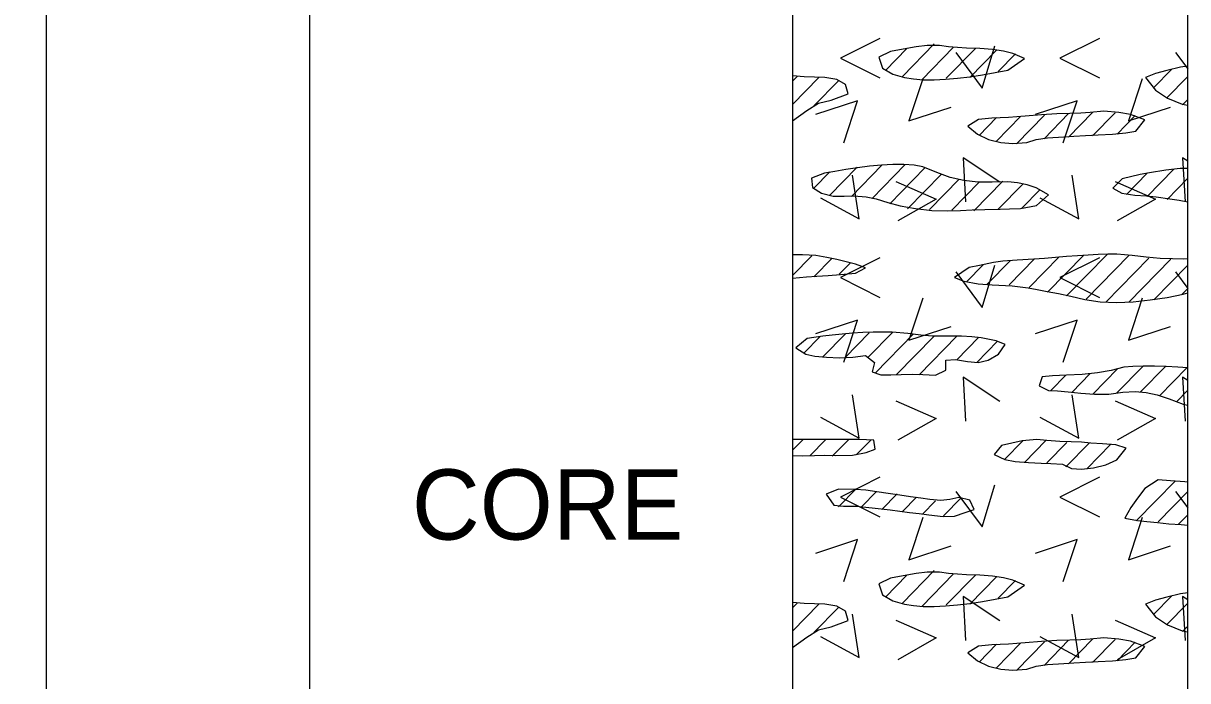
# Model space of a CAD drawing. Extents: x 0 to 0.833, y -0.32 to 0.608.
# Drawn here: x 0.7228 to 0.8333, y -0.0591 to 0.0033 of the extents above; entities that cross this region are included whole.
import ezdxf

# ---------------------------------------------------------------- set-up
doc = ezdxf.new("R2010")
doc.units = 0

msp = doc.modelspace()

# ---------------------------------------------------------------- linework, layer by layer
for points in [[(0, -0.32004), (0.83333, -0.32004), (0.83333, 0.60833), (0, 0.60833)], [(0.81233, 0.00099), (0.81063, 0.00111), (0.80977, 0.00124), (0.8086, 0.00125), (0.80755, 0.0011), (0.80632, 0.0009), (0.80513, 0.00066), (0.80403, 0.00014), (0.80436, -0.00092), (0.80536, -0.00149), (0.80647, -0.00179), (0.8073, -0.00194), (0.80824, -0.00201), (0.80926, -0.00202), (0.81035, -0.00197), (0.81149, -0.00187), (0.81267, -0.00172), (0.81386, -0.00154), (0.81506, -0.00132), (0.81625, -0.00109), (0.81783, -0.00001), (0.81673, 0.00049), (0.81585, 0.00069), (0.8148, 0.00085), (0.81361, 0.00095)], [(0.83265, -0.00082), (0.83136, -0.00113), (0.83028, -0.00141), (0.82934, -0.0018), (0.83026, -0.003), (0.83142, -0.00377), (0.83279, -0.00434), (0.83333, -0.00444), (0.83333, -0.00073)], [(0.79583, -0.00592), (0.79719, -0.00493), (0.79831, -0.00423), (0.79951, -0.00396), (0.80111, -0.00336), (0.80086, -0.00247), (0.80002, -0.002), (0.79889, -0.0018), (0.79791, -0.00177), (0.79694, -0.00172), (0.79583, -0.00163)], [(0.82537, -0.00498), (0.82408, -0.00513), (0.82319, -0.00518), (0.82214, -0.00521), (0.82091, -0.00525), (0.81947, -0.00534), (0.81792, -0.00546), (0.81632, -0.00558), (0.81475, -0.00567), (0.81348, -0.00577), (0.81247, -0.00641), (0.81337, -0.00717), (0.81444, -0.00768), (0.81561, -0.00796), (0.81675, -0.00807), (0.81807, -0.00796), (0.81896, -0.00768), (0.82003, -0.00754), (0.82157, -0.00742), (0.82253, -0.00736), (0.82362, -0.0073), (0.82483, -0.00724), (0.82618, -0.00717), (0.82745, -0.00706), (0.82842, -0.00689), (0.82927, -0.00583), (0.82791, -0.00532), (0.82679, -0.00512)], [(0.79885, -0.01089), (0.79763, -0.01135), (0.79773, -0.01224), (0.79859, -0.01277), (0.7997, -0.01306), (0.80074, -0.01305), (0.80165, -0.01304), (0.80281, -0.01312), (0.80377, -0.01333), (0.80486, -0.01368), (0.80606, -0.01398), (0.80751, -0.01425), (0.80905, -0.01444), (0.81052, -0.01447), (0.81177, -0.01441), (0.81289, -0.01437), (0.81408, -0.01433), (0.81553, -0.01429), (0.81642, -0.01427), (0.81745, -0.01423), (0.81897, -0.01396), (0.82011, -0.01293), (0.81896, -0.01226), (0.8181, -0.01199), (0.81717, -0.01179), (0.81626, -0.01169), (0.81479, -0.01175), (0.81343, -0.01174), (0.8121, -0.01159), (0.8108, -0.01129), (0.80953, -0.01083), (0.8082, -0.01028), (0.80736, -0.01012), (0.8064, -0.01005), (0.80536, -0.01005), (0.80427, -0.01011), (0.80314, -0.01022), (0.80201, -0.01036), (0.8009, -0.01053), (0.79984, -0.01071)], [(0.83263, -0.01044), (0.83126, -0.01058), (0.82969, -0.01084), (0.82883, -0.01102), (0.82712, -0.01143), (0.82623, -0.0123), (0.82708, -0.01279), (0.82831, -0.01297), (0.82941, -0.01304), (0.83033, -0.01313), (0.83165, -0.01331), (0.83253, -0.01345), (0.83333, -0.0136), (0.83333, -0.01045)], [(0.79583, -0.02084), (0.79715, -0.02073), (0.79814, -0.02066), (0.79922, -0.02058), (0.80039, -0.0205), (0.80179, -0.02038), (0.80275, -0.01986), (0.80179, -0.01952), (0.80091, -0.0193), (0.80003, -0.01908), (0.79909, -0.01888), (0.79803, -0.01871), (0.79677, -0.01862), (0.79583, -0.01864)], [(0.82816, -0.02309), (0.82978, -0.02292), (0.83137, -0.02267), (0.8329, -0.02236), (0.83333, -0.02225), (0.83333, -0.01901), (0.83295, -0.01905), (0.83188, -0.01902), (0.83071, -0.01897), (0.82938, -0.01887), (0.82807, -0.0187), (0.82662, -0.01858), (0.82576, -0.01858), (0.82484, -0.01861), (0.82387, -0.01866), (0.82286, -0.01872), (0.82182, -0.0188), (0.82077, -0.01889), (0.81973, -0.01897), (0.81872, -0.01905), (0.81715, -0.01914), (0.81579, -0.01923), (0.81491, -0.01937), (0.81357, -0.01964), (0.8126, -0.01985), (0.81121, -0.02077), (0.8121, -0.02113), (0.81345, -0.02138), (0.81479, -0.02147), (0.81668, -0.02157), (0.81818, -0.02177), (0.81905, -0.02192), (0.82, -0.0221), (0.82107, -0.02231), (0.82225, -0.02257), (0.82357, -0.02286), (0.82501, -0.02308), (0.82656, -0.02315)], [(0.79708, -0.02807), (0.79794, -0.02825), (0.79904, -0.02836), (0.80028, -0.0284), (0.80156, -0.02834), (0.80274, -0.02819), (0.80361, -0.02885), (0.80338, -0.02975), (0.80422, -0.03002), (0.80517, -0.03004), (0.80613, -0.02998), (0.8072, -0.02995), (0.80818, -0.02998), (0.80939, -0.03005), (0.81037, -0.02959), (0.81038, -0.02864), (0.8113, -0.02858), (0.81244, -0.02876), (0.81346, -0.02887), (0.81438, -0.02862), (0.81539, -0.02807), (0.81601, -0.02716), (0.81517, -0.02679), (0.81374, -0.02651), (0.81285, -0.02642), (0.81187, -0.02636), (0.81, -0.02636), (0.8091, -0.02634), (0.808, -0.02627), (0.80678, -0.02611), (0.8053, -0.02598), (0.80443, -0.02597), (0.80349, -0.02598), (0.80251, -0.02602), (0.80152, -0.02608), (0.80054, -0.02616), (0.79959, -0.02625), (0.7987, -0.02635), (0.79722, -0.02658), (0.79614, -0.02745)], [(0.83241, -0.02929), (0.83129, -0.02923), (0.83017, -0.02919), (0.8291, -0.02919), (0.82811, -0.02923), (0.82728, -0.02931), (0.82608, -0.02961), (0.82476, -0.02984), (0.8233, -0.02998), (0.82183, -0.03006), (0.82051, -0.03012), (0.81951, -0.03022), (0.81922, -0.03108), (0.82013, -0.0315), (0.82097, -0.03155), (0.822, -0.03165), (0.82318, -0.03178), (0.82448, -0.03187), (0.82584, -0.03185), (0.82719, -0.03168), (0.82836, -0.03161), (0.8294, -0.0317), (0.83043, -0.03193), (0.83156, -0.03232), (0.83291, -0.03281), (0.83333, -0.03289), (0.83333, -0.02937)], [(0.79583, -0.0377), (0.79676, -0.03771), (0.79792, -0.03769), (0.79882, -0.03766), (0.79992, -0.0377), (0.80151, -0.03766), (0.80282, -0.0374), (0.80367, -0.03708), (0.80354, -0.03624), (0.80216, -0.03616), (0.79583, -0.03616)], [(0.81822, -0.03835), (0.81944, -0.03841), (0.82033, -0.03845), (0.82145, -0.03852), (0.82229, -0.03893), (0.82324, -0.03897), (0.82438, -0.03887), (0.82555, -0.03858), (0.82662, -0.03808), (0.82749, -0.03698), (0.82651, -0.03668), (0.82524, -0.03658), (0.82413, -0.03651), (0.82324, -0.03641), (0.82226, -0.03639), (0.82121, -0.03636), (0.81995, -0.03627), (0.81902, -0.03616), (0.81761, -0.03629), (0.81566, -0.03674), (0.81496, -0.03758), (0.81598, -0.03807), (0.81695, -0.03824)], [(0.83305, -0.0402), (0.83171, -0.04009), (0.83054, -0.03999), (0.82925, -0.04081), (0.82857, -0.04172), (0.82792, -0.04261), (0.82735, -0.04364), (0.82858, -0.04386), (0.82945, -0.04396), (0.83045, -0.04406), (0.83155, -0.04416), (0.83272, -0.04425), (0.83333, -0.0443), (0.83333, -0.04021)], [(0.80066, -0.04251), (0.80188, -0.04251), (0.80339, -0.04264), (0.80423, -0.04274), (0.8051, -0.04285), (0.806, -0.04297), (0.80692, -0.04309), (0.80784, -0.0432), (0.80875, -0.04331), (0.81014, -0.04346), (0.81119, -0.04344), (0.81222, -0.0431), (0.81308, -0.04281), (0.81267, -0.04191), (0.8116, -0.04166), (0.81075, -0.04186), (0.80989, -0.04195), (0.80885, -0.04187), (0.80799, -0.04175), (0.80703, -0.04161), (0.806, -0.04145), (0.80492, -0.04128), (0.80384, -0.04112), (0.8028, -0.04099), (0.80182, -0.0409), (0.8002, -0.04089), (0.79901, -0.04136), (0.79974, -0.0424)], [(0.81233, -0.04901), (0.81063, -0.04889), (0.80977, -0.04876), (0.8086, -0.04875), (0.80755, -0.0489), (0.80632, -0.0491), (0.80513, -0.04934), (0.80403, -0.04986), (0.80436, -0.05092), (0.80536, -0.05149), (0.80647, -0.05179), (0.8073, -0.05194), (0.80824, -0.05201), (0.80926, -0.05202), (0.81035, -0.05197), (0.81149, -0.05187), (0.81267, -0.05172), (0.81386, -0.05154), (0.81506, -0.05132), (0.81625, -0.05109), (0.81783, -0.05001), (0.81673, -0.04951), (0.81585, -0.04931), (0.8148, -0.04915), (0.81361, -0.04905)], [(0.83265, -0.05082), (0.83136, -0.05113), (0.83028, -0.05141), (0.82934, -0.0518), (0.83026, -0.053), (0.83142, -0.05377), (0.83279, -0.05434), (0.83333, -0.05444), (0.83333, -0.05073)], [(0.79583, -0.05592), (0.79719, -0.05493), (0.79831, -0.05423), (0.79951, -0.05396), (0.80111, -0.05336), (0.80086, -0.05247), (0.80002, -0.052), (0.79889, -0.0518), (0.79791, -0.05177), (0.79694, -0.05172), (0.79583, -0.05163)], [(0.82537, -0.05498), (0.82408, -0.05513), (0.82319, -0.05518), (0.82214, -0.05521), (0.82091, -0.05525), (0.81947, -0.05534), (0.81792, -0.05546), (0.81632, -0.05558), (0.81475, -0.05567), (0.81348, -0.05577), (0.81247, -0.05641), (0.81337, -0.05717), (0.81444, -0.05768), (0.81561, -0.05796), (0.81675, -0.05807), (0.81807, -0.05796), (0.81896, -0.05768), (0.82003, -0.05754), (0.82157, -0.05742), (0.82253, -0.05736), (0.82362, -0.0573), (0.82483, -0.05724), (0.82618, -0.05717), (0.82745, -0.05706), (0.82842, -0.05689), (0.82927, -0.05583), (0.82791, -0.05532), (0.82679, -0.05512)]]:
    msp.add_lwpolyline(points, close=True)
for points in [[(0.725, 0.55417), (0.725, -0.27517)], [(0.75, 0.55417), (0.75, -0.27517)], [(0.75, 0.55417), (0.75, -0.27517)], [(0.79583, 0.55417), (0.79583, -0.27517)], [(0.725, 0.54167), (0.725, -0.27517)], [(0.83333, -0.27517), (0.83333, 0.50377)], [(0.80412, 0.00191), (0.80038, 0.00004), (0.80412, -0.00184)], [(0.80626, -0.0017), (0.80928, 0.0014)], [(0.81134, 0.00057), (0.81384, -0.0028), (0.81503, 0.0012)], [(0.82496, 0.00191), (0.82121, 0.00004), (0.82496, -0.00184)], [(0.80465, -0.00113), (0.80667, 0.00095)], [(0.80809, -0.00203), (0.81111, 0.00107)], [(0.81041, -0.00186), (0.81318, 0.00097)], [(0.81264, -0.00179), (0.81518, 0.00081)], [(0.81536, -0.00122), (0.81699, 0.00045)], [(0.83217, 0.00057), (0.83333, -0.00099)], [(0.8301, -0.00279), (0.83184, -0.00101)], [(0.7963, -0.00167), (0.79583, -0.00216)], [(0.79834, -0.0018), (0.79583, -0.00437)], [(0.79786, -0.0045), (0.80023, -0.00208)], [(0.80818, -0.00192), (0.80687, -0.00592), (0.81087, -0.0046)], [(0.82901, -0.00192), (0.8277, -0.00592), (0.8317, -0.0046)], [(0.83131, -0.00377), (0.83333, -0.00169)], [(0.80069, -0.008), (0.802, -0.004), (0.798, -0.00531)], [(0.82152, -0.008), (0.82284, -0.004), (0.81884, -0.00531)], [(0.83285, -0.00439), (0.83333, -0.0039)], [(0.81514, -0.00787), (0.81748, -0.00547)], [(0.81709, -0.00809), (0.81974, -0.00537)], [(0.8197, -0.00763), (0.82203, -0.00523)], [(0.82202, -0.00747), (0.8243, -0.00513)], [(0.82431, -0.00733), (0.82644, -0.00514)], [(0.82663, -0.00717), (0.82834, -0.00542)], [(0.81519, -0.00561), (0.81354, -0.0073)], [(0.81551, -0.01172), (0.81201, -0.00941), (0.81226, -0.0136)], [(0.83333, -0.00973), (0.83284, -0.00941), (0.83309, -0.0136)], [(0.79938, -0.01075), (0.79786, -0.0123)], [(0.79933, -0.01301), (0.80195, -0.01032)], [(0.80142, -0.01308), (0.8043, -0.01013)], [(0.80653, -0.01006), (0.8034, -0.01327)], [(0.80506, -0.01378), (0.8084, -0.01036)], [(0.80997, -0.01096), (0.80675, -0.01426)], [(0.82751, -0.0129), (0.82945, -0.01092)], [(0.83203, -0.01049), (0.82949, -0.01309)], [(0.79847, -0.01321), (0.80215, -0.01521), (0.80153, -0.01108)], [(0.80562, -0.01166), (0.80946, -0.01334), (0.80581, -0.01541)], [(0.81164, -0.01146), (0.80884, -0.01433)], [(0.81353, -0.01174), (0.81094, -0.01439)], [(0.81303, -0.01446), (0.81579, -0.01163)], [(0.81534, -0.0143), (0.81768, -0.01191)], [(0.8193, -0.01321), (0.82299, -0.01521), (0.82236, -0.01108)], [(0.82645, -0.01166), (0.83029, -0.01334), (0.82664, -0.01541)], [(0.83138, -0.01337), (0.83333, -0.01137)], [(0.8176, -0.0142), (0.81934, -0.01242)], [(0.83333, -0.01358), (0.83333, -0.01358)], [(0.79765, -0.01873), (0.79583, -0.0206)], [(0.82004, -0.02217), (0.82346, -0.01867)], [(0.82569, -0.01859), (0.82184, -0.02253)], [(0.82775, -0.01869), (0.8237, -0.02284)], [(0.7996, -0.01895), (0.79786, -0.02073)], [(0.8013, -0.01942), (0.80027, -0.02048)], [(0.80412, -0.01892), (0.80038, -0.02079), (0.80412, -0.02267)], [(0.81134, -0.02026), (0.81384, -0.02363), (0.81503, -0.01963)], [(0.81392, -0.01958), (0.81235, -0.02119)], [(0.8143, -0.02141), (0.8165, -0.01916)], [(0.8164, -0.02147), (0.81879, -0.01902)], [(0.81829, -0.02175), (0.82114, -0.01883)], [(0.82496, -0.01892), (0.82121, -0.02079), (0.82496, -0.02267)], [(0.82964, -0.01896), (0.82557, -0.02314)], [(0.83173, -0.01903), (0.82774, -0.02312)], [(0.83333, -0.01961), (0.83012, -0.0229)], [(0.83217, -0.02026), (0.83333, -0.02182)], [(0.83281, -0.02236), (0.83333, -0.02182)], [(0.80818, -0.02275), (0.80687, -0.02675), (0.81087, -0.02544)], [(0.82901, -0.02275), (0.8277, -0.02675), (0.8317, -0.02544)], [(0.80069, -0.02883), (0.802, -0.02483), (0.798, -0.02614)], [(0.82152, -0.02883), (0.82284, -0.02483), (0.81884, -0.02614)], [(0.79844, -0.02639), (0.79691, -0.02796)], [(0.79871, -0.02833), (0.80085, -0.02614)], [(0.80083, -0.02837), (0.80311, -0.02603)], [(0.80534, -0.02596), (0.80299, -0.02837)], [(0.80367, -0.02988), (0.80732, -0.02614)], [(0.80571, -0.03), (0.80924, -0.02639)], [(0.81142, -0.02637), (0.80785, -0.03002)], [(0.81141, -0.0286), (0.81348, -0.02647)], [(0.81528, -0.02684), (0.81331, -0.02886)], [(0.82433, -0.03186), (0.82666, -0.02947)], [(0.82909, -0.02919), (0.82656, -0.03178)], [(0.82885, -0.03165), (0.83122, -0.02922)], [(0.83325, -0.02936), (0.83065, -0.03202)], [(0.81551, -0.03256), (0.81201, -0.03024), (0.81226, -0.03443)], [(0.82035, -0.03151), (0.82176, -0.03006)], [(0.82233, -0.03169), (0.82408, -0.0299)], [(0.83333, -0.03057), (0.83284, -0.03024), (0.83309, -0.03443)], [(0.79847, -0.03404), (0.80215, -0.03604), (0.80153, -0.03191)], [(0.8193, -0.03404), (0.82299, -0.03604), (0.82236, -0.03191)], [(0.83333, -0.03148), (0.83227, -0.03258)], [(0.80562, -0.03249), (0.80946, -0.03418), (0.80581, -0.03624)], [(0.82645, -0.03249), (0.83029, -0.03418), (0.82664, -0.03624)], [(0.79583, -0.03719), (0.79681, -0.03619)], [(0.79898, -0.03617), (0.79747, -0.03772)], [(0.80116, -0.03615), (0.79959, -0.03776)], [(0.80328, -0.03619), (0.80188, -0.03762)], [(0.8177, -0.03629), (0.81596, -0.03807)], [(0.81988, -0.03627), (0.81785, -0.03835)], [(0.82185, -0.03646), (0.81997, -0.03839)], [(0.824, -0.03647), (0.82178, -0.03875)], [(0.82601, -0.03663), (0.82378, -0.03891)], [(0.80412, -0.03975), (0.80038, -0.04163), (0.80412, -0.0435)], [(0.82496, -0.03975), (0.82121, -0.04163), (0.82496, -0.0435)], [(0.80188, -0.04085), (0.8002, -0.04257)], [(0.81134, -0.04109), (0.81384, -0.04447), (0.81503, -0.04047)], [(0.83217, -0.04008), (0.82844, -0.04389)], [(0.8038, -0.04109), (0.80237, -0.04256)], [(0.80575, -0.04131), (0.80429, -0.0428)], [(0.80758, -0.04165), (0.80627, -0.04299)], [(0.80941, -0.04198), (0.80816, -0.04326)], [(0.81188, -0.04167), (0.81016, -0.04342)], [(0.83333, -0.0411), (0.83052, -0.04398)], [(0.83217, -0.04109), (0.83333, -0.04265)], [(0.80818, -0.04358), (0.80687, -0.04758), (0.81087, -0.04627)], [(0.82901, -0.04358), (0.8277, -0.04758), (0.8317, -0.04627)], [(0.83333, -0.04331), (0.83245, -0.04421)], [(0.80069, -0.04966), (0.802, -0.04566), (0.798, -0.04698)], [(0.82152, -0.04966), (0.82284, -0.04566), (0.81884, -0.04698)], [(0.80626, -0.0517), (0.80928, -0.0486)], [(0.80465, -0.05113), (0.80667, -0.04905)], [(0.80809, -0.05203), (0.81111, -0.04893)], [(0.81041, -0.05186), (0.81318, -0.04903)], [(0.81264, -0.05179), (0.81518, -0.04919)], [(0.81536, -0.05122), (0.81699, -0.04955)], [(0.7963, -0.05167), (0.79583, -0.05216)], [(0.79834, -0.0518), (0.79583, -0.05437)], [(0.81551, -0.05339), (0.81201, -0.05108), (0.81226, -0.05526)], [(0.8301, -0.05279), (0.83184, -0.05101)], [(0.83131, -0.05376), (0.83333, -0.05169)], [(0.83333, -0.0514), (0.83284, -0.05108), (0.83309, -0.05526)], [(0.79786, -0.0545), (0.80023, -0.05208)], [(0.79847, -0.05487), (0.80215, -0.05687), (0.80153, -0.05275)], [(0.8193, -0.05487), (0.82299, -0.05687), (0.82236, -0.05275)], [(0.80562, -0.05333), (0.80946, -0.05501), (0.80581, -0.05707)], [(0.82645, -0.05333), (0.83029, -0.05501), (0.82664, -0.05707)], [(0.83285, -0.05439), (0.83333, -0.0539)], [(0.8197, -0.05763), (0.82203, -0.05523)], [(0.82202, -0.05747), (0.8243, -0.05513)], [(0.82431, -0.05733), (0.82644, -0.05514)], [(0.81519, -0.05561), (0.81354, -0.0573)], [(0.81514, -0.05787), (0.81748, -0.05547)], [(0.81709, -0.05809), (0.81974, -0.05537)], [(0.82663, -0.05717), (0.82834, -0.05542)]]:
    msp.add_lwpolyline(points)

# ---------------------------------------------------------------- texts
msp.add_text('CORE', height=0.006667).set_placement((0.75971, -0.04567))

doc.saveas('drawing.dxf')
